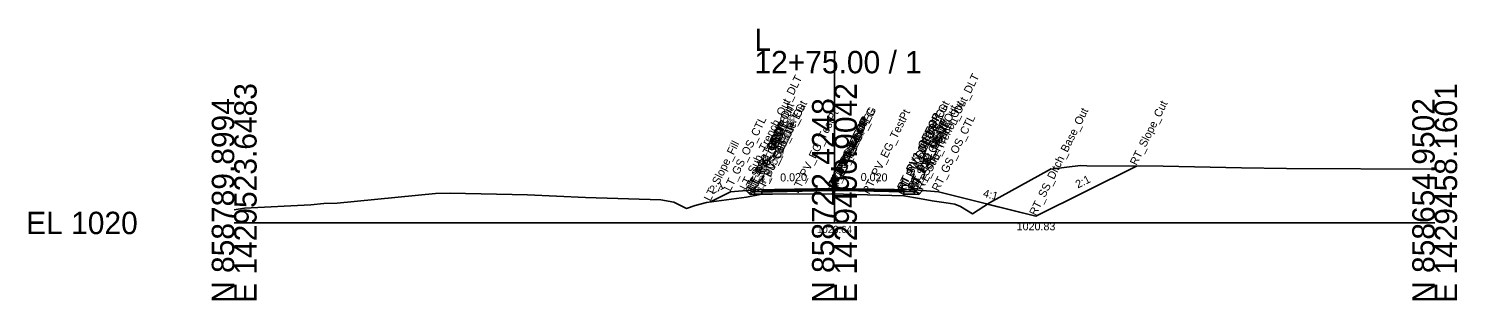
# Model space of a CAD drawing. Extents: x -26 to 153, y -10 to 13058.
# Drawn here: x -25.7 to 152.8, y 2490.3 to 2524.3 of the extents above; entities that cross this region are included whole.
import ezdxf

# ---------------------------------------------------------------- set-up
doc = ezdxf.new("R2010")
doc.units = 0
for name, color, linetype in [('Default', 7, 'Continuous'), ('Exist Cross Section Cell', 7, 'Continuous'), ('Exist XS Ground Line', 7, 'Continuous'), ('Old_Level_50', 7, 'Continuous'), ('Prop CMT Pvmt Course 1', 7, 'Continuous'), ('Prop CMT Pvmt Course 1 Wedge', 7, 'Continuous'), ('Prop CMT Pvmt Course 2', 7, 'Continuous'), ('Prop CMT Pvmt Course 2 Wedge', 7, 'Continuous'), ('Prop CMT Pvmt Surface', 7, 'Continuous'), ('Prop CMT Pvmt Surface Shoulder', 7, 'Continuous'), ('Prop CMT Pvmt Wedge Surface 1', 7, 'Continuous'), ('Prop CMT Pvmt Wedge Surface 2', 7, 'Continuous'), ('Prop CMT Shld Paved Course 1', 7, 'Continuous'), ('Prop CMT Shld Paved Course 2', 7, 'Continuous'), ('Prop CMT Slope Grass', 7, 'Continuous'), ('Prop CMT Subgrade Daylight Point', 7, 'Continuous'), ('Prop CMT Subgrade Earthwork', 7, 'Continuous'), ('Prop XS Ditch Standard Text', 7, 'Continuous'), ('Prop XS Dump Level', 7, 'Continuous'), ('Prop XS SE Text', 7, 'Continuous'), ('Prop XS Side Slope Text', 7, 'Continuous')]:
    doc.layers.add(name, color=color, linetype=linetype)

msp = doc.modelspace()

# ---------------------------------------------------------------- linework, layer by layer
at = {"layer": 'Exist Cross Section Cell'}
for p, q in [((75, 2500), (75, 2521.51)), ((0, 2500), (75, 2500)), ((75, 2500), (150, 2500))]:
    msp.add_line(p, q, dxfattribs=at)
at = {"layer": 'Exist XS Ground Line'}
msp.add_lwpolyline([(0, 2501.63), (1.28, 2501.83), (9.57, 2502.27), (11.2, 2502.43), (12.85, 2502.47), (25.15, 2503.67), (27, 2503.72), (36.65, 2503.51), (43.88, 2503.19), (53.32, 2502.88), (54.93, 2502.61), (56.53, 2501.81), (57.6, 2502.2), (59.02, 2502.57), (63.99, 2503.24), (65.94, 2503.6), (67.24, 2503.61), (74.69, 2503.65), (75, 2503.64), (76.15, 2503.61), (83.67, 2503.37), (85.63, 2503.04), (87.2, 2502.77), (88.94, 2502.51), (90.06, 2502.33), (90.74, 2502.06), (92.23, 2501.14), (94.36, 2502.52), (102.01, 2506.74), (105.73, 2507.17), (106.54, 2507.15), (116.08, 2507.11), (125.87, 2506.9), (131.47, 2506.82), (150, 2506.72)], dxfattribs=at)
at = {"layer": 'Old_Level_50'}
msp.add_line((112.75, 2507.12), (106.54, 2507.15), dxfattribs=at)
for points in [[(106.54, 2507.15), (105.73, 2507.17), (102.01, 2506.74), (94.36, 2502.52), (94.1, 2502.35)], [(94.1, 2502.35), (100.17, 2500.83), (112.75, 2507.12)]]:
    msp.add_lwpolyline(points, dxfattribs=at)
at = {"layer": 'Prop CMT Pvmt Course 1'}
for points in [[(75, 2504.32), (65, 2504.12)], [(65, 2504.12), (65, 2503.91)], [(65, 2503.91), (65.94, 2503.93)], [(65.94, 2504.01), (75, 2504.19)], [(65.94, 2503.93), (65.94, 2504.01)], [(75, 2504.11), (75, 2504.32)], [(75, 2504.32), (85, 2504.12)], [(75, 2504.11), (75, 2504.32)], [(75, 2504.19), (75, 2504.11), (75, 2504.11)], [(83.67, 2504.02), (75, 2504.19)], [(75, 2504.19), (75, 2504.11), (75, 2504.11)], [(83.67, 2503.94), (83.67, 2504.02)], [(85, 2503.91), (83.67, 2503.94)], [(85, 2504.12), (85, 2503.91)]]:
    msp.add_lwpolyline(points, dxfattribs=at)
at = {"layer": 'Prop CMT Pvmt Course 1 Wedge'}
for points in [[(65.94, 2504.01), (65.94, 2504.01), (67.24, 2504.04), (74.69, 2504.19), (75, 2504.19)], [(75, 2504.07), (74.69, 2504.06), (67.24, 2503.91), (65.94, 2503.89), (65.94, 2503.89)], [(65.94, 2503.89), (65.94, 2504.01)], [(75, 2504.19), (75, 2504.07)], [(75, 2504.19), (76.15, 2504.17), (83.67, 2504.02)], [(75, 2504.07), (75, 2504.19)], [(83.67, 2503.89), (76.15, 2504.05), (75, 2504.07)], [(83.67, 2504.02), (83.67, 2503.89)]]:
    msp.add_lwpolyline(points, dxfattribs=at)
at = {"layer": 'Prop CMT Pvmt Course 2'}
for points in [[(65.94, 2503.93), (65, 2503.91)], [(65, 2503.91), (65, 2503.58)], [(65, 2503.58), (65.94, 2503.6)], [(65.94, 2503.6), (65.94, 2503.93)], [(83.67, 2503.6), (83.67, 2503.94)], [(83.67, 2503.94), (85, 2503.91)], [(85, 2503.58), (83.67, 2503.6)], [(85, 2503.91), (85, 2503.58)]]:
    msp.add_lwpolyline(points, dxfattribs=at)
at = {"layer": 'Prop CMT Pvmt Course 2 Wedge'}
for points in [[(65.94, 2503.93), (65.94, 2503.93), (67.24, 2503.95), (74.69, 2504.1), (75, 2504.11)], [(65.94, 2503.6), (65.94, 2503.93)], [(75, 2503.64), (74.69, 2503.65), (67.24, 2503.61), (65.94, 2503.6), (65.94, 2503.6)], [(75, 2504.11), (75, 2503.64)], [(75, 2504.11), (76.15, 2504.09), (83.67, 2503.94)], [(75, 2503.64), (75, 2504.11)], [(83.67, 2503.37), (76.15, 2503.61), (75, 2503.64)], [(83.67, 2503.94), (83.67, 2503.37)]]:
    msp.add_lwpolyline(points, dxfattribs=at)
at = {"layer": 'Prop CMT Pvmt Surface'}
for points in [[(75, 2504.32), (65, 2504.12)], [(75, 2504.32), (85, 2504.12)]]:
    msp.add_lwpolyline(points, dxfattribs=at)
at = {"layer": 'Prop CMT Pvmt Surface Shoulder'}
for points in [[(65, 2504.12), (65, 2504.12)], [(85, 2504.12), (85, 2504.12)]]:
    msp.add_lwpolyline(points, dxfattribs=at)
at = {"layer": 'Prop CMT Pvmt Wedge Surface 1'}
for points in [[(65, 2503.91), (65, 2504.12)], [(65.94, 2503.93), (65, 2503.91)], [(75, 2504.19), (65.94, 2504.01)], [(65.94, 2504.01), (65.94, 2503.93)], [(75, 2504.19), (83.67, 2504.02)], [(83.67, 2504.02), (83.67, 2503.94)], [(83.67, 2503.94), (85, 2503.91)], [(85, 2503.91), (85, 2504.12)]]:
    msp.add_lwpolyline(points, dxfattribs=at)
at = {"layer": 'Prop CMT Pvmt Wedge Surface 2'}
for points in [[(65, 2503.91), (65, 2504.12)], [(75, 2504.11), (65, 2503.91)], [(75, 2504.11), (85, 2503.91)], [(85, 2503.91), (85, 2504.12)]]:
    msp.add_lwpolyline(points, dxfattribs=at)
at = {"layer": 'Prop CMT Shld Paved Course 1'}
for points in [[(65, 2504.12), (64.79, 2503.91)], [(64.79, 2503.91), (65, 2503.91)], [(65, 2504.12), (65, 2504.12)], [(65, 2503.91), (65, 2504.12)], [(85, 2504.12), (85, 2504.12)], [(85, 2504.12), (85.21, 2503.91)], [(85, 2503.91), (85, 2504.12)], [(85.21, 2503.91), (85, 2503.91)]]:
    msp.add_lwpolyline(points, dxfattribs=at)
at = {"layer": 'Prop CMT Shld Paved Course 2'}
for points in [[(64.79, 2503.91), (64.45, 2503.57)], [(64.45, 2503.57), (65, 2503.58)], [(65, 2503.91), (64.79, 2503.91)], [(64.79, 2503.91), (64.79, 2503.91)], [(65, 2503.58), (65, 2503.91)], [(85, 2503.91), (85.21, 2503.91)], [(85, 2503.58), (85, 2503.91)], [(85.55, 2503.57), (85, 2503.58)], [(85.21, 2503.91), (85.21, 2503.91)], [(85.21, 2503.91), (85.55, 2503.57)]]:
    msp.add_lwpolyline(points, dxfattribs=at)
at = {"layer": 'Prop CMT Slope Grass'}
for points in [[(85, 2504.12), (88, 2503.88), (100.17, 2500.83), (112.75, 2507.12)], [(65, 2504.12), (62, 2503.88), (59.51, 2502.64)]]:
    msp.add_lwpolyline(points, dxfattribs=at)
at = {"layer": 'Prop CMT Subgrade Earthwork'}
for points in [[(64.45, 2503.57), (63.98, 2504.04)], [(65, 2503.58), (64.45, 2503.57)], [(65.94, 2503.6), (65, 2503.58)], [(65.94, 2503.6), (65.96, 2503.6)], [(83.67, 2503.6), (83.65, 2503.37)], [(83.67, 2503.6), (85, 2503.58)], [(85, 2503.58), (85.55, 2503.57)], [(85.55, 2503.57), (86.02, 2504.04)]]:
    msp.add_lwpolyline(points, dxfattribs=at)

# ---------------------------------------------------------------- texts
at = {"layer": 'Default'}
msp.add_text('-', height=0.0001, dxfattribs=at).set_placement((0, 2500))
at = {"layer": 'Exist Cross Section Cell'}
for s, p in [('L', (65, 2521.51)), ('12+75.00 / 1', (65, 2518.71)), ('EL 1020', (-26, 2498.6))]:
    msp.add_text(s, height=2.8, dxfattribs=at).set_placement(p)
for s, p in [('E 1429523.6483', (2.8, 2490)), ('E 1429490.9042', (77.8, 2490)), ('E 1429458.1601', (152.8, 2490)), ('N 858789.8994', (0, 2490)), ('N 858722.4248', (75, 2490)), ('N 858654.9502', (150, 2490))]:
    msp.add_text(s, height=2.8, rotation=90, dxfattribs=at).set_placement(p)
at = {"layer": 'Prop CMT Subgrade Daylight Point'}
msp.add_text('1023.64', height=0.9, dxfattribs=at).set_placement((72.83, 2498.74))
at = {"layer": 'Prop XS Ditch Standard Text'}
msp.add_text('1020.83', height=1, dxfattribs=at).set_placement((97.77, 2499.08))
at = {"layer": 'Prop XS Dump Level'}
for s, p in [('LT_Sub_Trench_Out_DLT', (63.98, 2504.04)), ('RT_Sub_Trench_Out_DLT', (86.02, 2504.04)), ('LT_Sub_Trench_Out', (64.45, 2503.57)), ('LT_PS2_Shelf_Out', (64.79, 2503.91)), ('LT_PV_OEEOP_EG', (65.94, 2503.6)), ('LT_PV_Sub_Tie_Out', (65.96, 2503.6)), ('LT_PV_EG_TestPt', (70.47, 2503.63)), ('RT_PV_IEEOP_EG', (75, 2503.64)), ('LT_PV_IEEOP_EG', (75, 2503.64)), ('RT_PV_EG_TestPt', (79.33, 2503.51)), ('RT_PV_Sub_Tie_Out', (83.65, 2503.37)), ('RT_PV_OEEOP_EG', (83.67, 2503.37)), ('RT_PV1_OEEOP', (83.67, 2504.02)), ('RT_PS2_Shelf_Out', (85.21, 2503.91)), ('RT_Sub_Trench_Out', (85.55, 2503.57)), ('RT_SS_Ditch_Base_Out', (100.17, 2500.83)), ('RT_Slope_Cut', (112.75, 2507.12)), ('LT_GS_OS_CTL', (62, 2503.88)), ('LT_PS2_OEOP', (64.79, 2503.91)), ('LT_PV1_OEOT', (65, 2504.12)), ('LT_PS1_OEOP', (65, 2504.12)), ('LT_PV2_OEOT', (65, 2503.91)), ('LT_Sub_OEOT', (65, 2503.58)), ('LT_PV1_OEEOP', (65.94, 2504.01)), ('LT_PV2_OEEOP', (65.94, 2503.93)), ('LT_Sub_OEEOP', (65.94, 2503.6)), ('RT_PV1_IEEOP', (75, 2504.19)), ('RT_PV2_IEEOP', (75, 2504.11)), ('LT_PV1_IEEOP', (75, 2504.19)), ('LT_PV2_IEEOP', (75, 2504.11)), ('RT_PV2_OEEOP', (83.67, 2503.94)), ('RT_Sub_OEEOP', (83.67, 2503.6)), ('RT_PV1_OEOT', (85, 2504.12)), ('RT_PS1_OEOP', (85, 2504.12)), ('RT_PV2_OEOT', (85, 2503.91)), ('RT_Sub_OEOT', (85, 2503.58)), ('RT_PS2_OEOP', (85.21, 2503.91)), ('RT_GS_OS_CTL', (88, 2503.88)), ('LT_Slope_Fill', (59.51, 2502.64)), ('PV1_PGL', (75, 2504.32)), ('PV2_PGL', (75, 2504.11))]:
    msp.add_text(s, height=1, rotation=63.5833, dxfattribs=at).set_placement(p)
at = {"layer": 'Prop XS SE Text'}
for rotation, p in [(1.1458, (68.23, 2505.18)), (358.8542, (78.27, 2505.25))]:
    msp.add_text('0.020', height=1, rotation=rotation, dxfattribs=at).set_placement(p)
at = {"layer": 'Prop XS Side Slope Text'}
for s, rotation, p in [('2:1', 26.5651, (59.71, 2503.57)), ('2:1', 26.5651, (105.42, 2504.3)), ('4:1', 345.9638, (93.5, 2503.28))]:
    msp.add_text(s, height=1, rotation=rotation, dxfattribs=at).set_placement(p)

doc.saveas('drawing.dxf')
